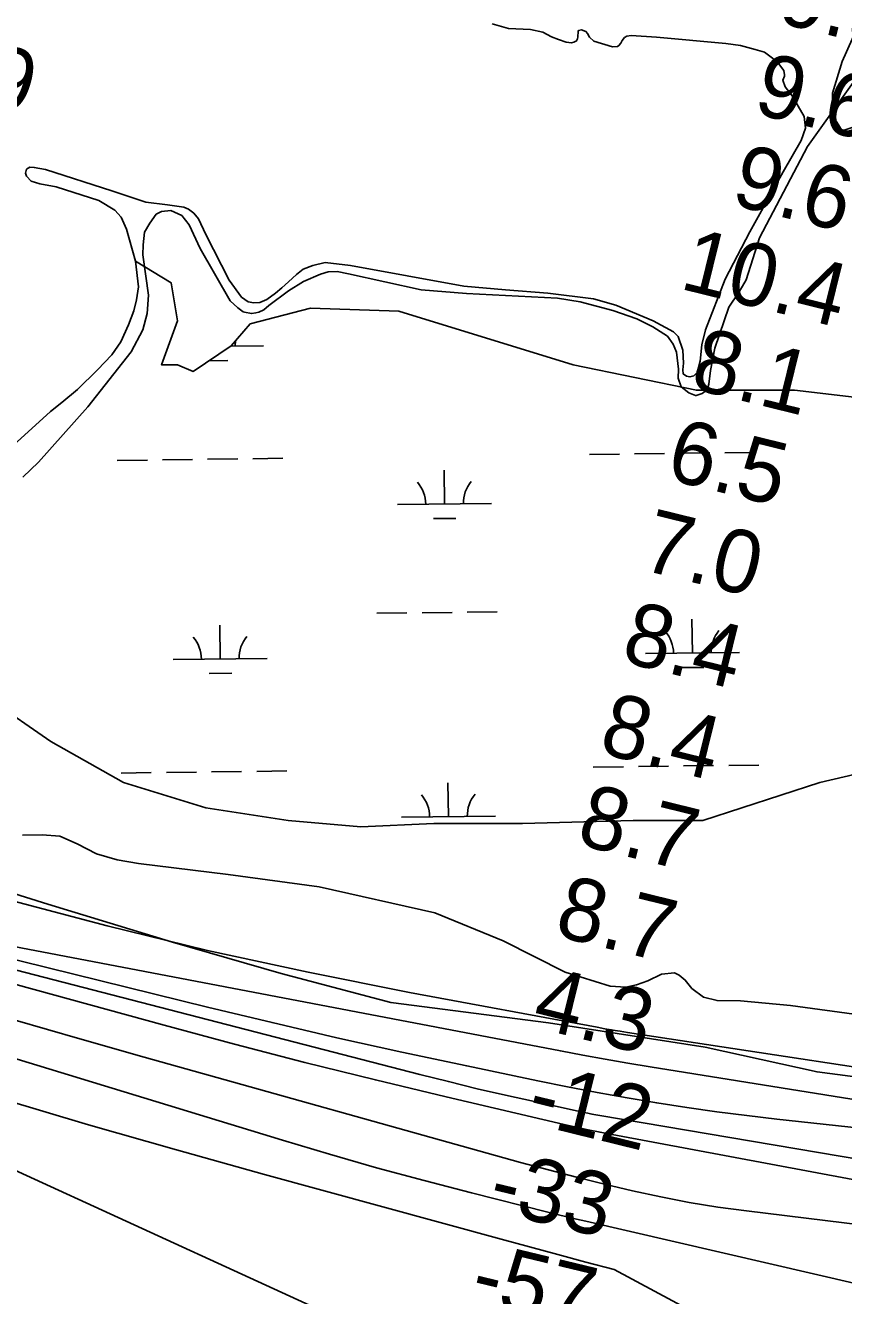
# Model space of a CAD drawing. Extents: x 3715084 to 3753216, y 488173 to 513963.
# Drawn here: x 3727308 to 3728178, y 500051 to 501402 of the extents above; entities that cross this region are included whole.
import ezdxf

# ---------------------------------------------------------------- set-up
doc = ezdxf.new("R2010")
doc.units = 0
for name, color, linetype in [('V-RIVR-EDGE', 7, 'Continuous'), ('V-RIVR-RANG', 7, 'Continuous'), ('V-SITE-VEGE', 7, 'Continuous'), ('V-TOPO-DPTH', 7, 'Continuous'), ('V-TOPO-MAJR', 7, 'Continuous'), ('V-TOPO-MINR', 7, 'Continuous'), ('V-TOPO-SHOR', 7, 'Continuous'), ('V-TOPO-WATR', 7, 'Continuous'), ('V-WETL-SWMP', 7, 'Continuous')]:
    doc.layers.add(name, color=color, linetype=linetype)

msp = doc.modelspace()

# ---------------------------------------------------------------- linework, layer by layer
at = {"layer": 'V-RIVR-EDGE'}
msp.add_lwpolyline([(3728365.3, 500260.7), (3728149.3, 500288.9), (3728030.5, 500315), (3727863.7, 500341.2), (3727696.2, 500362.6), (3727579.8, 500393.5), (3727464.1, 500426.8), (3727331.5, 500467.4), (3727182.1, 500514), (3727097.5, 500542.4), (3726997.4, 500573.3), (3726878, 500616.2), (3726767.7, 500660.3), (3726651.9, 500707.4), (3726508, 500772.6), (3726420.4, 500799.8), (3726332.9, 500843.3), (3726229.1, 500896.3), (3726123.6, 500955.4), (3725922.8, 501063.4), (3725804.1, 501124.9), (3725682.4, 501194.3)], dxfattribs=at)
at = {"layer": 'V-SITE-VEGE'}
for points in [[(3728002, 501036.6), (3728001.8, 501026.9), (3728005, 501017.5), (3728012.9, 501011.4), (3728020, 501008.5), (3728020.8, 501008.3), (3728027.1, 501010.5), (3728032.4, 501014.6), (3728034.3, 501020.5), (3728036.1, 501034.9), (3728040.7, 501058.8), (3728055.7, 501102.3), (3728065.7, 501117.5), (3728070, 501124.6), (3728073.9, 501131.6), (3728088.2, 501176.2), (3728139.2, 501273.3), (3728207.3, 501368.6)], [(3727304.9, 500921.4), (3727321.6, 500937.4), (3727374, 500996.3), (3727420.2, 501054.9), (3727432.6, 501078.4), (3727437.2, 501095.7), (3727438.7, 501115.2), (3727432.5, 501158.1), (3727432.8, 501168.8), (3727434.2, 501182), (3727440.2, 501191.8), (3727446.9, 501201.3), (3727452.6, 501204.3), (3727462.2, 501205.3), (3727473.9, 501200), (3727482, 501189.8), (3727493.7, 501164.7), (3727525.4, 501109), (3727533.5, 501101.6), (3727539.2, 501097.3), (3727540.8, 501096.9), (3727548.1, 501095.5), (3727552.6, 501096.3), (3727556, 501097.1), (3727561.1, 501099.7), (3727566.6, 501104.1), (3727587.6, 501119.9), (3727603.5, 501129.8), (3727621.4, 501137.6), (3727629.6, 501139.9), (3727639.1, 501140.4), (3727651.1, 501137.9), (3727728.6, 501120.8), (3727776.5, 501117), (3727873.3, 501112.1), (3727897.6, 501108.1), (3727932.1, 501098.9), (3727957.9, 501089.8), (3727974.8, 501081.6), (3727990.2, 501071.6), (3727996.2, 501062.9), (3727999.8, 501054.5), (3728002, 501036.6)], [(3728196.5, 500349.2), (3728121.2, 500359.4), (3728067.8, 500364.3), (3728043.1, 500364.8), (3728028.5, 500368.5), (3728016.3, 500377.6), (3728009.3, 500386.6), (3728002.8, 500391.7), (3727997.9, 500394.4), (3727983.9, 500393), (3727969.3, 500385.7), (3727957.3, 500381.5), (3727946.1, 500379.1), (3727929.5, 500380), (3727881.4, 500395), (3727815.6, 500428.3), (3727743, 500458), (3727619.9, 500485.7), (3727523.2, 500498.8), (3727428, 500510.5), (3727405.3, 500514.3), (3727383.2, 500520.9), (3727362.6, 500531.3), (3727344.5, 500539.7), (3727325.5, 500541.2), (3727304.5, 500540.6)]]:
    msp.add_lwpolyline(points, dxfattribs=at)
at = {"layer": 'V-TOPO-DPTH'}
for points in [[(3727045.8, 500470.2), (3727501.3, 500357.8), (3727570, 500341.3), (3727638.8, 500325.2), (3727707.9, 500309.9), (3727777, 500295.2), (3727852.4, 500279.5), (3727883.9, 500273.1), (3727915.6, 500267.1), (3727947.3, 500261.4), (3727979, 500255.9), (3728010.9, 500251), (3728042.7, 500246.4), (3728074.7, 500242.3), (3728106.7, 500238.6), (3728697.3, 500174.7)], [(3727045.8, 500470.2), (3727501.3, 500357.8), (3727570, 500341.3), (3727638.8, 500325.2), (3727707.9, 500309.9), (3727777, 500295.2), (3727852.4, 500279.5), (3727883.9, 500273.1), (3727915.6, 500267.1), (3727947.3, 500261.4), (3727979, 500255.9), (3728010.9, 500251), (3728042.7, 500246.4), (3728074.7, 500242.3), (3728106.7, 500238.6), (3728697.3, 500174.7)], [(3728740.8, 500210.2), (3727948, 500330.8), (3727939.9, 500332.1), (3727931.8, 500333.4), (3727923.7, 500334.8), (3727915.6, 500336.3), (3727716, 500373.4), (3727608.4, 500394.8), (3727501.3, 500418.1), (3727394.8, 500444.3), (3727288.7, 500472.3)], [(3728312.6, 500151.1), (3727931.4, 500222.1), (3727918.6, 500224.6), (3727905.9, 500227.1), (3727893.2, 500229.9), (3727880.5, 500232.8), (3727755.1, 500262.2), (3727679.9, 500280.3), (3727604.8, 500298.9), (3727529.9, 500318.5), (3727455.2, 500338.5), (3727058.5, 500447.4)], [(3727058.5, 500447.4), (3727455.2, 500338.5), (3727529.9, 500318.5), (3727604.8, 500298.9), (3727679.9, 500280.3), (3727755.1, 500262.2), (3727880.5, 500232.8), (3727893.2, 500229.9), (3727905.9, 500227.1), (3727918.6, 500224.6), (3727931.4, 500222.1), (3728312.6, 500151.1)], [(3727164, 500343.4), (3727580.9, 500216.2), (3727630.9, 500201.3), (3727681.1, 500186.9), (3727731.5, 500173.3), (3727782, 500160.2), (3727863, 500139.7), (3727873.2, 500137.2), (3727883.3, 500134.7), (3727893.5, 500132.3), (3727903.7, 500129.9), (3728193.2, 500062.9)], [(3727164, 500343.4), (3727580.9, 500216.2), (3727630.9, 500201.3), (3727681.1, 500186.9), (3727731.5, 500173.3), (3727782, 500160.2), (3727863, 500139.7), (3727873.2, 500137.2), (3727883.3, 500134.7), (3727893.5, 500132.3), (3727903.7, 500129.9), (3728193.2, 500062.9)], [(3728677.2, 500067), (3728074.3, 500140.9), (3728043.9, 500145.1), (3728013.5, 500150), (3727983.4, 500155.8), (3727953.3, 500162.2), (3727923.4, 500169.3), (3727893.6, 500176.7), (3727863.9, 500184.5), (3727834.2, 500192.6), (3727434.1, 500304.6), (3727365.5, 500324), (3727297, 500343.9)], [(3728677.2, 500067), (3728074.3, 500140.9), (3728043.9, 500145.1), (3728013.5, 500150), (3727983.4, 500155.8), (3727953.3, 500162.2), (3727923.4, 500169.3), (3727893.6, 500176.7), (3727863.9, 500184.5), (3727834.2, 500192.6), (3727434.1, 500304.6), (3727365.5, 500324), (3727297, 500343.9)]]:
    msp.add_lwpolyline(points, dxfattribs=at)
at = {"layer": 'V-TOPO-MAJR'}
msp.add_lwpolyline([(3728272.2, 499896.9), (3727933.8, 500078.7), (3727903.7, 500086.6), (3727873.6, 500094.6), (3727843.5, 500102.7), (3727813.4, 500110.9), (3727562.1, 500179.6), (3727468.3, 500205.8), (3727374.7, 500232.6), (3727281.3, 500260.4)], dxfattribs=at)
at = {"layer": 'V-TOPO-MINR'}
for points in [[(3728697.3, 500174.7), (3728106.7, 500238.6), (3728074.7, 500242.3), (3728042.7, 500246.4), (3728010.9, 500251), (3727979, 500255.9), (3727947.3, 500261.4), (3727915.6, 500267.1), (3727883.9, 500273.1), (3727852.4, 500279.5), (3727777, 500295.2), (3727707.9, 500309.9), (3727638.8, 500325.2), (3727570, 500341.3), (3727501.3, 500357.8), (3727045.8, 500470.2)], [(3728659.9, 500117.1), (3727918.3, 500242.5), (3727914.1, 500243.2), (3727910, 500244), (3727905.8, 500244.8), (3727901.7, 500245.7), (3727848.9, 500257.2), (3727818.3, 500264), (3727787.9, 500271), (3727757.5, 500278.5), (3727727.2, 500286.1), (3727051.2, 500460.8)], [(3728312.6, 500151.1), (3727931.4, 500222.1), (3727918.6, 500224.6), (3727905.9, 500227.1), (3727893.2, 500229.9), (3727880.5, 500232.8), (3727755.1, 500262.2), (3727679.9, 500280.3), (3727604.8, 500298.9), (3727529.9, 500318.5), (3727455.2, 500338.5), (3727058.5, 500447.4)], [(3728204.1, 500256.9), (3727972.1, 500294.3), (3727948.1, 500298.3), (3727924.2, 500302.4), (3727900.3, 500306.7), (3727876.5, 500311.2), (3727256.1, 500429.6)], [(3728193.2, 500062.9), (3727903.7, 500129.9), (3727893.5, 500132.3), (3727883.3, 500134.7), (3727873.2, 500137.2), (3727863, 500139.7), (3727782, 500160.2), (3727731.5, 500173.3), (3727681.1, 500186.9), (3727630.9, 500201.3), (3727580.9, 500216.2), (3727164, 500343.4)], [(3728677.2, 500067), (3728074.3, 500140.9), (3728043.9, 500145.1), (3728013.5, 500150), (3727983.4, 500155.8), (3727953.3, 500162.2), (3727923.4, 500169.3), (3727893.6, 500176.7), (3727863.9, 500184.5), (3727834.2, 500192.6), (3727434.1, 500304.6), (3727365.5, 500324), (3727297, 500343.9)], [(3727686.3, 500005.5), (3727160.1, 500246.6)]]:
    msp.add_lwpolyline(points, dxfattribs=at)
at = {"layer": 'V-TOPO-SHOR'}
for points in [[(3727803.8, 501403.9), (3727821.3, 501398.8), (3727844.8, 501397.7), (3727857.8, 501394.8), (3727867, 501389.8), (3727874.6, 501387), (3727882.6, 501384.2), (3727888.2, 501383.7), (3727890.9, 501384.4), (3727893.7, 501385.7), (3727894.8, 501388), (3727895.2, 501390.1), (3727895.4, 501395.6), (3727895.7, 501396.7), (3727898.9, 501397.4), (3727903.7, 501395.7), (3727905.2, 501393.6), (3727907.5, 501389.6), (3727912.2, 501385.5), (3727931.9, 501379.4), (3727937.3, 501379.6), (3727938.7, 501380.6), (3727940.7, 501383.4), (3727942, 501386), (3727944.7, 501389.1), (3727947, 501390.6), (3727951.7, 501391.3), (3727978.7, 501389.7), (3728052.2, 501382.9), (3728067.8, 501380.8), (3728083.7, 501376.6), (3728093.3, 501373.6), (3728100.4, 501368.5), (3728107.2, 501362.9), (3728114.1, 501354.3)], [(3728051.5, 501132.2), (3728077.9, 501182.5), (3728113.2, 501246.2), (3728132.6, 501279.7), (3728137.1, 501292.7), (3728135.5, 501305.3), (3728123, 501327.3), (3728115.5, 501336.9), (3728113.1, 501344), (3728114.8, 501348.2), (3728114.6, 501349.5), (3728114.1, 501354.3)], [(3727409.1, 501065.4), (3727417.5, 501083.5), (3727422.9, 501098.5), (3727426, 501110.3), (3727427.8, 501124.1), (3727424.9, 501151.3), (3727415.3, 501185.3), (3727409.6, 501198.3), (3727402.9, 501205.7), (3727385.7, 501215.7), (3727340.4, 501230.5), (3727323, 501233.6), (3727313.8, 501236.5), (3727309, 501241.6), (3727308, 501245), (3727309, 501249.1), (3727312.3, 501251.3), (3727317.1, 501251.1), (3727329.1, 501248.8), (3727399.8, 501226.2), (3727435.7, 501214.1), (3727458.9, 501211.2), (3727476.1, 501208.6), (3727481.2, 501206.6), (3727486.9, 501202.3), (3727491.7, 501196.2), (3727499.4, 501179.7), (3727524.4, 501131.2), (3727537.6, 501113.1), (3727544.4, 501108), (3727550.5, 501107), (3727557, 501107.5), (3727564.4, 501110.4), (3727573.7, 501117.2), (3727580.3, 501122.9), (3727587.4, 501129.2), (3727595.8, 501137.3), (3727603.1, 501142.9), (3727613.3, 501146.8), (3727626.3, 501149.8), (3727653.3, 501146.8), (3727774, 501124.6), (3727818.3, 501120.8), (3727863.2, 501117.2), (3727911.7, 501111.4), (3727935.6, 501104.6), (3727975.2, 501087.8), (3727996.6, 501076.3), (3728001.7, 501071.2), (3728006.7, 501056.6), (3728007.5, 501042.8), (3728006.5, 501035.7), (3728007.1, 501031.4), (3728010.5, 501028.9), (3728014.2, 501028.1), (3728018.4, 501029.5), (3728021.9, 501032.8), (3728025.2, 501044.9), (3728026.9, 501062.2), (3728030.6, 501078.4), (3728051.5, 501132.2)], [(3727295.1, 500955.7), (3727334.5, 500991.5), (3727346.3, 501001), (3727363, 501014.8), (3727384.4, 501035.6), (3727399.5, 501051.8), (3727409.1, 501065.4)]]:
    msp.add_lwpolyline(points, dxfattribs=at)
at = {"layer": 'V-TOPO-WATR'}
msp.add_lwpolyline([(3728740.8, 500210.2), (3727948, 500330.8), (3727939.9, 500332.1), (3727931.8, 500333.4), (3727923.7, 500334.8), (3727915.6, 500336.3), (3727716, 500373.4), (3727608.4, 500394.8), (3727501.3, 500418.1), (3727394.8, 500444.3), (3727288.7, 500472.3)], dxfattribs=at)
at = {"layer": 'V-WETL-SWMP'}
for p, q in [((3727526.5, 501061), (3727560.7, 501061.4)), ((3727503, 501045.3), (3727522.9, 501045.5)), ((3727907.3, 500945.7), (3727939.3, 500946.1)), ((3727955.3, 500946.3), (3727987.3, 500946.7)), ((3728003.3, 500946.9), (3728035.3, 500947.3)), ((3728051.3, 500947.5), (3728083.3, 500947.9)), ((3727405.4, 500939.4), (3727437.4, 500939.8)), ((3727453.4, 500940), (3727485.4, 500940.4)), ((3727501.4, 500940.6), (3727533.4, 500941)), ((3727549.4, 500941.2), (3727581.4, 500941.6)), ((3727753.3, 500893), (3727752.9, 500929)), ((3727703.3, 500892.4), (3727803.3, 500893.7)), ((3727741.5, 500877.4), (3727765.5, 500877.7)), ((3727681.4, 500776.7), (3727713.4, 500777.1)), ((3727729.4, 500777.3), (3727761.4, 500777.7)), ((3727777.4, 500777.9), (3727809.4, 500778.3)), ((3728016.8, 500734.4), (3728016.3, 500770.4)), ((3727514.9, 500728.2), (3727514.5, 500764.2)), ((3727966.8, 500733.8), (3728066.8, 500735.1)), ((3727464.9, 500727.6), (3727564.9, 500728.8)), ((3728005, 500718.9), (3728029, 500719.2)), ((3727503.1, 500712.6), (3727527.1, 500712.9)), ((3727505.6, 500608), (3727537.6, 500608.4)), ((3727553.6, 500608.6), (3727585.6, 500609)), ((3727911.4, 500613.1), (3727943.4, 500613.5)), ((3727959.4, 500613.7), (3727991.4, 500614.1)), ((3728007.4, 500614.3), (3728039.4, 500614.7)), ((3728055.4, 500614.8), (3728087.4, 500615.2)), ((3727409.6, 500606.8), (3727441.6, 500607.2)), ((3727457.6, 500607.4), (3727489.6, 500607.8)), ((3727757.5, 500560.4), (3727757, 500596.4)), ((3727707.5, 500559.8), (3727807.5, 500561))]:
    msp.add_line(p, q, dxfattribs=at)
for points in [[(3728206.2, 501299.9), (3728175.9, 501289.8), (3728165.8, 501306.7), (3728165.8, 501330.2), (3728175.9, 501363.8), (3728192.7, 501400.9)], [(3727295.1, 500955.7), (3727334.5, 500991.5), (3727346.3, 501001), (3727363, 501014.8), (3727384.4, 501035.6), (3727399.5, 501051.8), (3727409.1, 501065.4), (3727417.5, 501083.5), (3727422.9, 501098.5), (3727426, 501110.3), (3727427.8, 501124.1), (3727424.9, 501151.3), (3727424.9, 501151.4), (3727462.7, 501128.3), (3727469.4, 501088), (3727452.6, 501040.9), (3727469.4, 501040.9), (3727486.2, 501034.1), (3727526.6, 501061.1), (3727546.8, 501084.6), (3727610.7, 501101.4), (3727704.9, 501098.1), (3727889.9, 501040.9), (3728021.1, 501014), (3728071.6, 501014), (3728125.4, 501014), (3728212.9, 501003.9)], [(3728297, 500630.4), (3728152.4, 500596.8), (3728027.9, 500556.4), (3727953.9, 500556.4), (3727836.1, 500553.1), (3727741.9, 500553.1), (3727664.5, 500549.7), (3727587.2, 500556.4), (3727499.7, 500569.9), (3727412.2, 500596.8), (3727334.8, 500640.5), (3727270.9, 500684.3)]]:
    msp.add_lwpolyline(points, dxfattribs=at)
for centre, start, end in [((3727566, 501062), 173.1664, 181.4878), ((3727698.1, 500892.8), 359.9442, 41.4878), ((3727808.6, 500894.2), 139.9442, 181.4878), ((3727961.5, 500734.2), 359.9442, 41.4878), ((3728072, 500735.6), 139.9442, 181.4878), ((3727459.7, 500728), 359.9442, 41.4878), ((3727570.1, 500729.3), 139.9442, 181.4878), ((3727702.3, 500560.2), 359.9442, 41.4878), ((3727812.7, 500561.5), 139.9442, 181.4878)]:
    msp.add_arc(centre, 35.2, start, end, dxfattribs=at)

# ---------------------------------------------------------------- texts
at = {"layer": 'V-RIVR-RANG'}
for s, rotation, p in [('9.9', 346.1583, (3728105, 501405.9)), ('3.9', 344.3683, (3727188.1, 501339.5)), ('9.6', 346.1583, (3728079.8, 501309.2)), ('9.6', 346.1583, (3728056.1, 501212)), ('10.4', 346.1583, (3728001.9, 501122.4)), ('8.1', 346.1583, (3728012.8, 501016.7)), ('6.5', 346.1583, (3727986.8, 500920.1)), ('7.0', 346.1583, (3727960.3, 500823.6)), ('8.4', 346.1583, (3727939.4, 500725.8)), ('8.4', 346.1583, (3727915.7, 500628.6)), ('8.7', 346.1583, (3727892, 500531.5)), ('8.7', 346.1583, (3727868.4, 500434.3)), ('4.3', 346.1583, (3727844.7, 500337.2)), ('-12', 346.1583, (3727838.6, 500235.7)), ('-33', 346.4376, (3727797.6, 500142.4)), ('-57', 346.4376, (3727778.5, 500044.1))]:
    msp.add_text(s, height=67, rotation=rotation, dxfattribs=at).set_placement(p)

doc.saveas('drawing.dxf')
